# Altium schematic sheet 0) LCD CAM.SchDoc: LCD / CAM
size A3; Origin: Eagle; DocumentNumber: 6; SheetNumber: 6; SheetTotal: 9
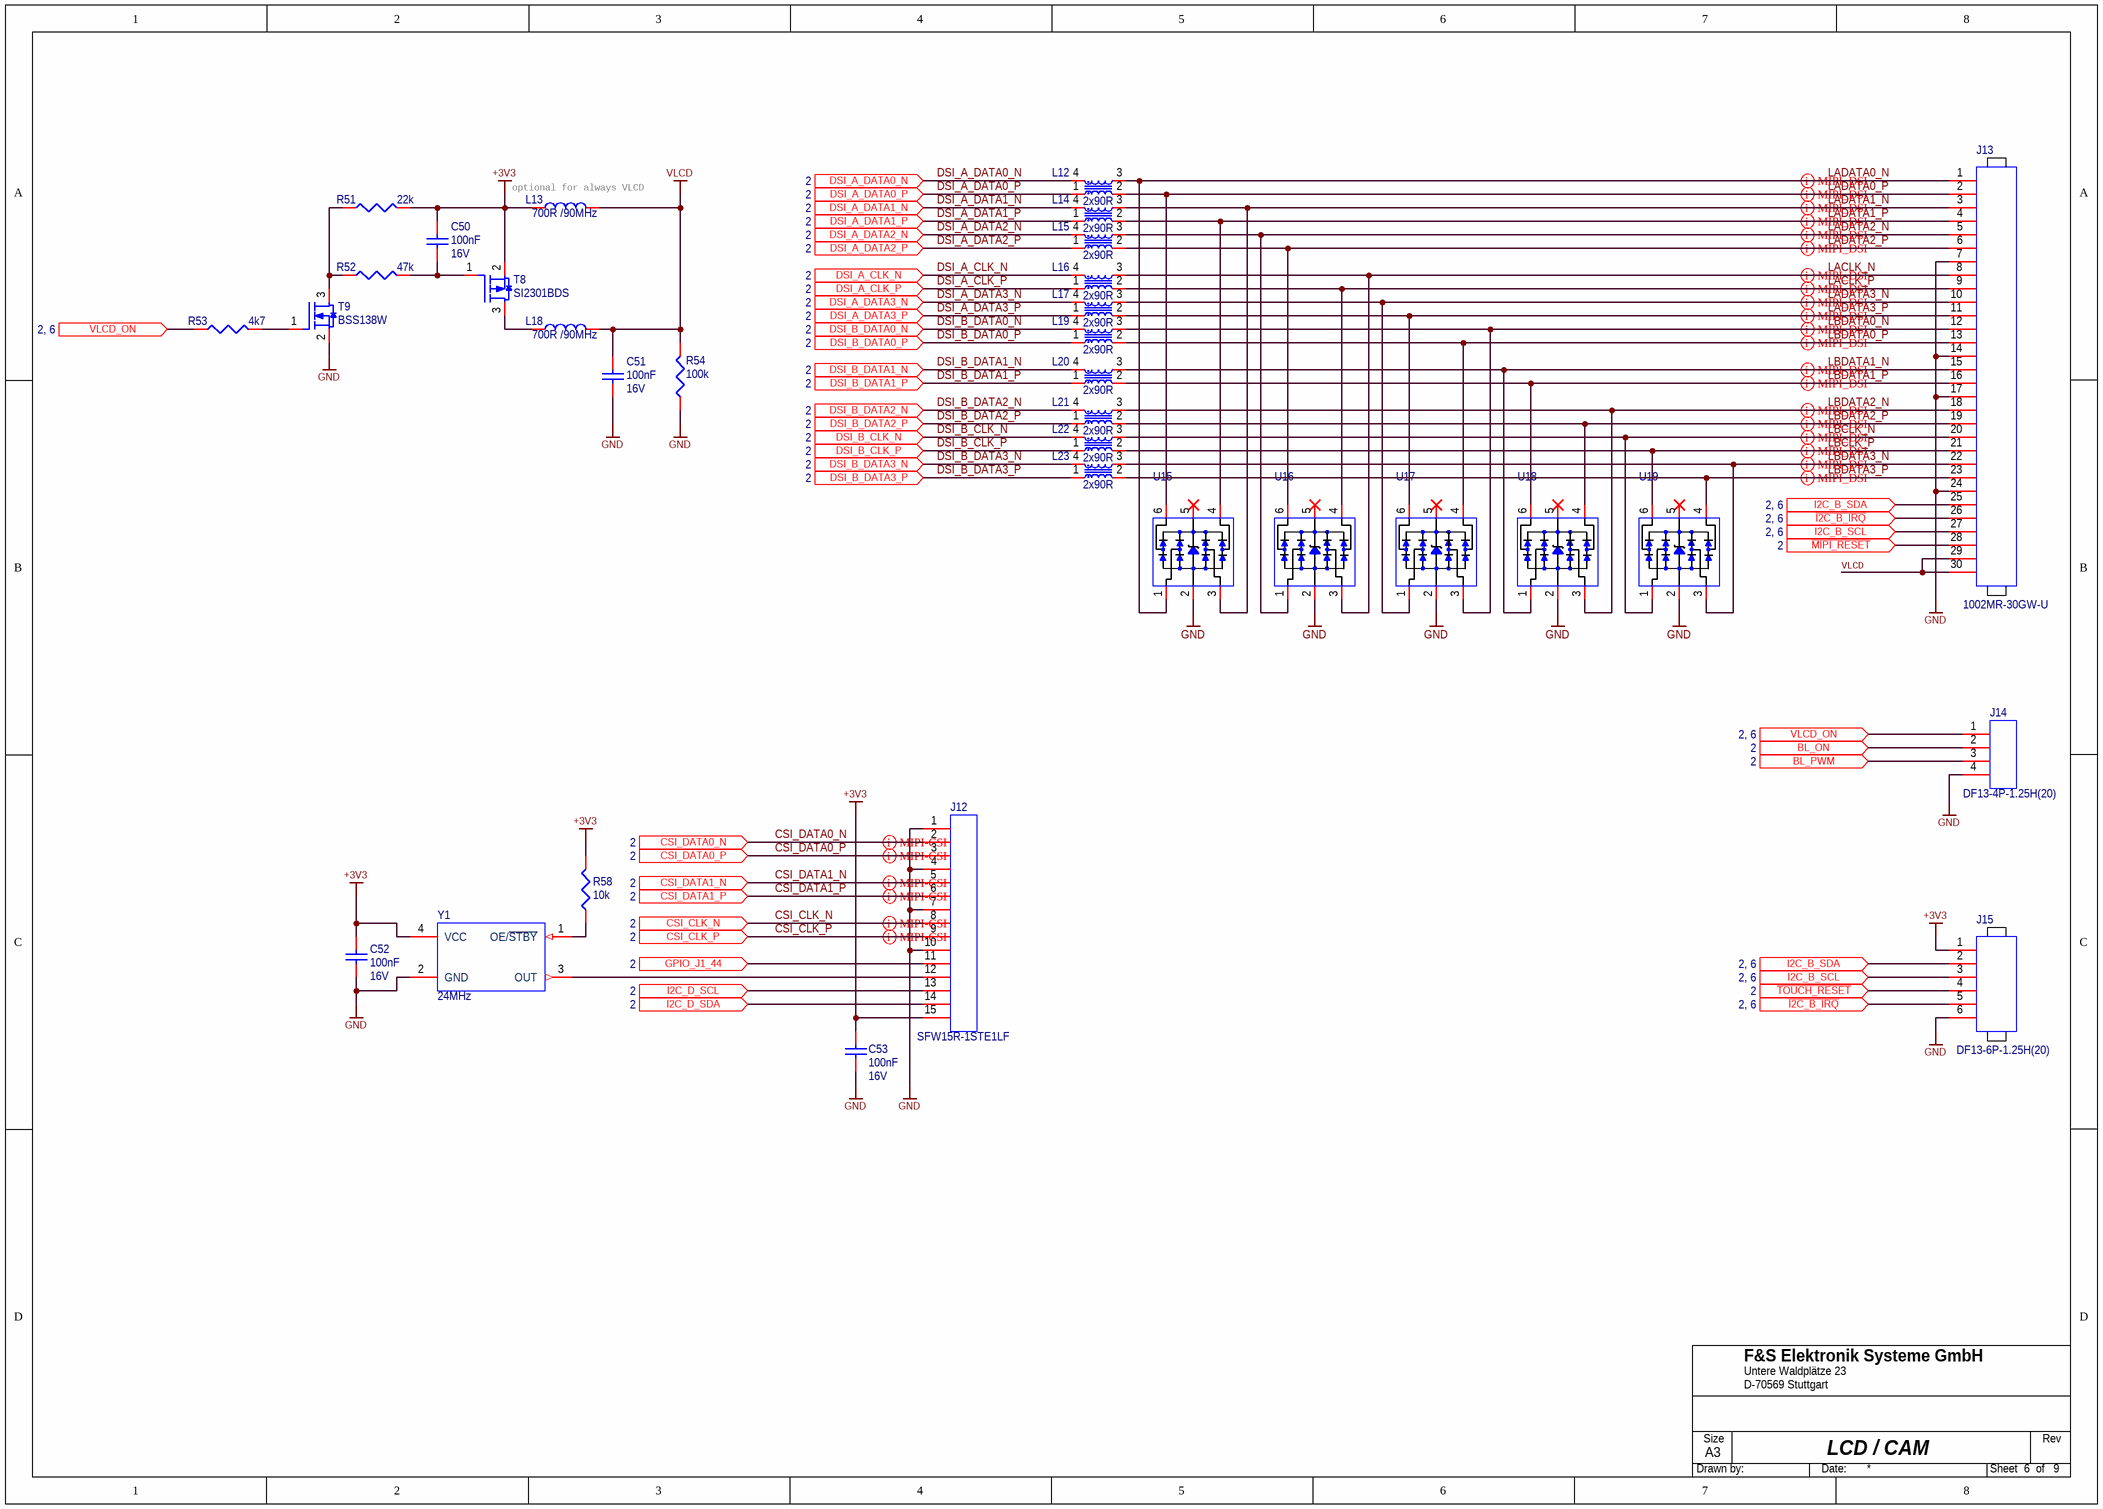
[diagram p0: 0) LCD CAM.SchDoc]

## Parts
C50  100nF  Voltage: 16V  [C0402]
C51  100nF  Voltage: 16V  [C0402]
C52  100nF  Voltage: 16V  [C0402]
C53  100nF  Voltage: 16V  [C0402]
J12  SFW15R-1STE1LF  [SFW15R-1STE1LF]
J13  1002MR-30GW-U  [JAE-30Pol.]
J14  DF13-4P-1.25H(20)  [DF13-4P-1.25H(20)]
J15  DF13-6P-1.25H(20)  [DF13-6P-1.25H(20)]
L12  2x90R  [DLP11SN900HL2L]
L13  700R /90MHz  [L1206]
L14  2x90R  [DLP11SN900HL2L]
L15  2x90R  [DLP11SN900HL2L]
L16  2x90R  [DLP11SN900HL2L]
L17  2x90R  [DLP11SN900HL2L]
L18  700R /90MHz  [L1206]
L19  2x90R  [DLP11SN900HL2L]
L20  2x90R  [DLP11SN900HL2L]
L21  2x90R  [DLP11SN900HL2L]
L22  2x90R  [DLP11SN900HL2L]
L23  2x90R  [DLP11SN900HL2L]
R51  22k  [R0402]
R52  47k  [R0402]
R53  4k7  [R0402]
R54  100k  [R0402]
R58  10k  [R0402]
T8  SI2301BDS  [SOT23-3]
T9  BSS138W  [SOT323 (SC70)]
U15  TVS Diode  [SOT23-6]  (value not drawn)
U16  TVS Diode  [SOT23-6]  (value not drawn)
U17  TVS Diode  [SOT23-6]  (value not drawn)
U18  TVS Diode  [SOT23-6]  (value not drawn)
U19  TVS Diode  [SOT23-6]  (value not drawn)
Y1  24MHz  [XTALD-4-302X205M]

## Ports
BL_ON (in, see 2), BL_PWM (in, see 2), CSI_CLK_N (in, see 2), CSI_CLK_P (in, see 2), CSI_DATA0_N (in, see 2), CSI_DATA0_P (in, see 2), CSI_DATA1_N (in, see 2), CSI_DATA1_P (in, see 2), DSI_A_CLK_N (in, see 2), DSI_A_CLK_P (in, see 2), DSI_A_DATA0_N (in, see 2), DSI_A_DATA0_P (in, see 2), DSI_A_DATA1_N (in, see 2), DSI_A_DATA1_P (in, see 2), DSI_A_DATA2_N (in, see 2), DSI_A_DATA2_P (in, see 2), DSI_A_DATA3_N (in, see 2), DSI_A_DATA3_P (in, see 2), DSI_B_CLK_N (in, see 2), DSI_B_CLK_P (in, see 2), DSI_B_DATA0_N (in, see 2), DSI_B_DATA0_P (in, see 2), DSI_B_DATA1_N (in, see 2), DSI_B_DATA1_P (in, see 2), DSI_B_DATA2_N (in, see 2), DSI_B_DATA2_P (in, see 2), DSI_B_DATA3_N (in, see 2), DSI_B_DATA3_P (in, see 2), GPIO_J1_44 (in, see 2), I2C_B_SCL (in, see 2, 6), I2C_B_SDA (in, see 2, 6), I2C_D_SCL (in, see 2), I2C_D_SDA (in, see 2), VLCD_ON (in, see 2, 6), ~{I2C_B_IRQ} (in, see 2, 6), ~{MIPI_RESET} (in, see 2), ~{TOUCH_RESET} (in, see 2)

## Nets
+3V3: C50.2 C52.2 C53.2 J12.15 J15.1 L13.1 R51.2 R58.2 T8.2 Y1.4(VCC)
GND: C51.1 C52.1 C53.1 J12.1 J12.4 J12.7 J12.10 J13.7 J13.14 J13.17 J13.24 J14.4 J15.6 R54.1 T9.2 U15.2(GND) U16.2(GND) U17.2(GND) U18.2(GND) U19.2(GND) Y1.2(GND)
VLCD: C51.2 J13.29 J13.30 L13.2 L18.2 R54.2
~{TOUCH_RESET}: J15.4 ; port ~{TOUCH_RESET}
BL_ON: J14.2 ; port BL_ON
BL_PWM: J14.3 ; port BL_PWM
CSI_CLK_N: J12.8 ; port CSI_CLK_N
CSI_CLK_P: J12.9 ; port CSI_CLK_P
CSI_DATA0_N: J12.2 ; port CSI_DATA0_N
CSI_DATA0_P: J12.3 ; port CSI_DATA0_P
CSI_DATA1_N: J12.5 ; port CSI_DATA1_N
CSI_DATA1_P: J12.6 ; port CSI_DATA1_P
DSI_A_CLK_N: L16.4 ; port DSI_A_CLK_N
DSI_A_CLK_P: L16.1 ; port DSI_A_CLK_P
DSI_A_DATA0_N: L12.4 ; port DSI_A_DATA0_N
DSI_A_DATA0_P: L12.1 ; port DSI_A_DATA0_P
DSI_A_DATA1_N: L14.4 ; port DSI_A_DATA1_N
DSI_A_DATA1_P: L14.1 ; port DSI_A_DATA1_P
DSI_A_DATA2_N: L15.4 ; port DSI_A_DATA2_N
DSI_A_DATA2_P: L15.1 ; port DSI_A_DATA2_P
DSI_A_DATA3_N: L17.4 ; port DSI_A_DATA3_N
DSI_A_DATA3_P: L17.1 ; port DSI_A_DATA3_P
DSI_B_CLK_N: L22.4 ; port DSI_B_CLK_N
DSI_B_CLK_P: L22.1 ; port DSI_B_CLK_P
DSI_B_DATA0_N: L19.4 ; port DSI_B_DATA0_N
DSI_B_DATA0_P: L19.1 ; port DSI_B_DATA0_P
DSI_B_DATA1_N: L20.4 ; port DSI_B_DATA1_N
DSI_B_DATA1_P: L20.1 ; port DSI_B_DATA1_P
DSI_B_DATA2_N: L21.4 ; port DSI_B_DATA2_N
DSI_B_DATA2_P: L21.1 ; port DSI_B_DATA2_P
DSI_B_DATA3_N: L23.4 ; port DSI_B_DATA3_N
DSI_B_DATA3_P: L23.1 ; port DSI_B_DATA3_P
GPIO_J1_44: J12.11 ; port GPIO_J1_44
I2C_B_SCL: J13.27 J15.3 ; port I2C_B_SCL
I2C_B_SDA: J13.25 J15.2 ; port I2C_B_SDA
I2C_D_SCL: J12.13 ; port I2C_D_SCL
I2C_D_SDA: J12.14 ; port I2C_D_SDA
~{I2C_B_IRQ}: J13.26 J15.5 ; port ~{I2C_B_IRQ}
LACLK_N: J13.8 L16.3 U16.3(I/O3)
LACLK_P: J13.9 L16.2 U16.4(I/O4)
LADATA0_N: J13.1 L12.3 U15.1(I/O1)
LADATA0_P: J13.2 L12.2 U15.6(I/O6)
LADATA1_N: J13.3 L14.3 U15.3(I/O3)
LADATA1_P: J13.4 L14.2 U15.4(I/O4)
LADATA2_N: J13.5 L15.3 U16.1(I/O1)
LADATA2_P: J13.6 L15.2 U16.6(I/O6)
LADATA3_N: J13.10 L17.3 U17.1(I/O1)
LADATA3_P: J13.11 L17.2 U17.6(I/O6)
LBCLK_N: J13.20 L22.3 U19.1(I/O1)
LBCLK_P: J13.21 L22.2 U19.6(I/O6)
LBDATA0_N: J13.12 L19.3 U17.3(I/O3)
LBDATA0_P: J13.13 L19.2 U17.4(I/O4)
LBDATA1_N: J13.15 L20.3 U18.1(I/O1)
LBDATA1_P: J13.16 L20.2 U18.6(I/O6)
LBDATA2_N: J13.18 L21.3 U18.3(I/O3)
LBDATA2_P: J13.19 L21.2 U18.4(I/O4)
LBDATA3_N: J13.22 L23.3 U19.3(I/O3)
LBDATA3_P: J13.23 L23.2 U19.4(I/O4)
~{MIPI_RESET}: J13.28 ; port ~{MIPI_RESET}
VLCD_ON: J14.1 R53.1 ; port VLCD_ON
NetC50_1: C50.1 R52.2 T8.1
NetJ12_12: J12.12 Y1.3(OUT)
NetL18_1: L18.1 T8.3
NetR51_1: R51.1 R52.1 T9.3
NetR53_2: R53.2 T9.1
NetR58_1: R58.1 Y1.1(OE/~{STBY})

Not connected (* = marked no-connect by the designer): U15 5(VCC)*; U16 5(VCC)*; U17 5(VCC)*; U18 5(VCC)*; U19 5(VCC)*

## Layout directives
differential pair; differential pair class MIPI-CSI: CSI_CLK_N, CSI_CLK_P, CSI_DATA0_N, CSI_DATA0_P, CSI_DATA1_N, CSI_DATA1_P
differential pair; differential pair class MIPI-DSI: LACLK_N, LACLK_P, LADATA0_N, LADATA0_P, LADATA1_N, LADATA1_P, LADATA2_N, LADATA2_P, LADATA3_N, LADATA3_P, LBCLK_N, LBCLK_P, LBDATA0_N, LBDATA0_P, LBDATA1_N, LBDATA1_P, LBDATA2_N, LBDATA2_P, LBDATA3_N, LBDATA3_P

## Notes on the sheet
- (near L13) optional for always VLCD

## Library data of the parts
C50-C53 = 380: 100nF  10%  16V  X7R  0402; FS-EDV-Nummer: B.CKV.42; Class: Capacitor Ceramic; Tolerance: 10; ID: 380
J12 = 2726: FPC 15 pol. 1,0mm side / SMT; FS-EDV-Nummer: B.MBU.1R15PL.1; Class: Connector; ID: 2726
J13 = 2728: FPC 30 pol. 1.00mm side entry SMT; FS-EDV-Nummer: B.MBU.1R30PL.3; Class: Connector; ID: 2728
J14 = 2721: Stiftl. 4 pol. crimpable  liegend RM:1.25; FS-EDV-Nummer: B.MST.1R4PL.9; Class: Connector; ID: 2721
J15 = 2720: Stiftl. 6 pol. crimpable  liegend RM:1.25; FS-EDV-Nummer: B.MST.1R6PL.2; Class: Connector; ID: 2720
L12 L14-L17 L19-L23 = 2731: Common Mode Choke  20%  2x 90 Ohm  0504; FS-EDV-Nummer: B.EMVFER.13; Voltage: 5V; Power: 150mA; ID: 2731
L13 L18 = 2705: WE-CBF  25%  700R  90MHz  EMI  1206; Part Number: 74279218; FS-EDV-Nummer: B.EMVFER.5; Class: Ferit; ID: 2705
R51 = 179: 22k 1/16W 1% SMD 0402; FS-EDV-Nummer: B.R22K0.1; Tolerance: 1; ID: 179
R52 = 186: 47k 1/16W 1% SMD 0402; FS-EDV-Nummer: B.R47K0.1; Tolerance: 1; ID: 186
R53 = 184: 4k7 1/16W max 5% SMD 0402; FS-EDV-Nummer: B.R4K7.3; Tolerance: 5; ID: 184
R54 = 177: 100k 1/16W 1% SMD 0402; FS-EDV-Nummer: B.R100K.3; Tolerance: 1; ID: 177
R58 = 170: 10k 1/16W 1% SMD 0402; FS-EDV-Nummer: B.R10K.3; Tolerance: 1; ID: 170
T8 = 2691: Si2301BDS SOT-23 P-Kanal; FS-EDV-Nummer: B.TPMFP.2.S; Class: MOSFET; ID: 2691
T9 = 2689: BSS138W SOT323(SC-70) N-Kanal; FS-EDV-Nummer: B.TPMFN.10; Class: MOSFET; ID: 2689
U15-U19 = 2710: 4 Channel  5,5V  TVS Diode Array  SOT-23-6; Part Number: AOZ8904CIL; CLASS: ESD; FS-EDV-Nummer: B.EMVSUP.2; ID: 2710
Y1 = 2732: 24MHz SMD 3,2x2,5mm; Part Number: ASEMB-24.000MHZ-LC-T; FS-EDV-Nummer: B.OSZ.15; Class: Crystal Oscillator; Power: <10mA; Tolerance: 10ppm; ID: 2732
